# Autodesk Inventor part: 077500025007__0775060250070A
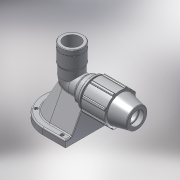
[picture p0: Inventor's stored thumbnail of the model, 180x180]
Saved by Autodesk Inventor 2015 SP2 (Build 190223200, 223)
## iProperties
Created: 2017-02
Part Number: 077500025007__0775060250070A
Material: PVC-Piping
Description: PLASSON WALL PLATE ELBOW 25-3/4"
Document SubType Name: Modeling
Designer: KIM
Mass: 92.6774 g
Surface Area: 199.44 cm^2
Volume: 66.1981 cm^3
Density: 1.4 g/cm^3
Appearance: Smooth - White
Author: KIM
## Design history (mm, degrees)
derived "07750.ipt"
feature "Solid1::07750.ipt"
feature "Solid2::07750.ipt"
tag "TaggingFeature1"
body "Solid1"
other parameters: "d2" = 25, "d4" = 6.75, "d5" = 20.25, "d7" = 54, "d9" = 11.57143, "d11" = 2.7, "d13" = 120 deg, "d14" = 37.5, "d15" = 12 deg, "d16" = 46.98, "d18" = 1.25, "d19" = 35 deg, "d20" = 17.5 deg, "d21" = 50.22, "d23" = 0, "d25" = 360 deg, "d27" = 1.08, "d33" = 0.5, "d42" = 29.97, "d43" = 1.62, "d46" = 0.75, "d51" = 81, "d68" = 2.7, "d76" = 24.117, "d77" = 20.9, "d79" = 9.6468, "d80" = 0.72351, "d83" = 0, "d84" = 0, "d91" = 40.5, "d93" = 58, "d94" = 24.117, "d95" = 16.8819, "d96" = 6.75, "d97" = 50 deg, "d98" = 21.7053, "d99" = 0.5, "d100" = 0.5, "d101" = 6.33333, "d112" = 19, "d113" = 33.7638, "d114" = 31.3521, "d115" = -38, "d116" = 7.6, "d118" = 7.6, "d119" = 0, "d120" = 0, "d121" = 90 deg, "d122" = 0, "d123" = 90 deg, "d124" = 1.62, "d126" = 7.6, "d127" = 0, "d128" = 1.52, "d129" = 1.52, "d130" = 6.08, "d131" = 0, "d132" = 1.62, "d133" = 0.81, "d134" = 4, "d135" = 8.1, "d136" = 4, "d137" = 4.05, "d138" = 46.17, "d139" = 12.15, "d141" = 0, "d_" = 25, "E_" = 54, "A_" = 81, "l_" = 58, "l_1" = 19, "Rp_" = 24.117, "A_2" = 38
